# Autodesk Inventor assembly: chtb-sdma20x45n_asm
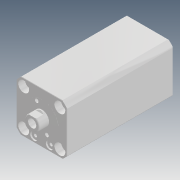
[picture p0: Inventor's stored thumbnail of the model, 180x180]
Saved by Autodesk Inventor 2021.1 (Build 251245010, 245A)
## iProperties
Created: 2018-05
Part Number: chtb-sdma20x45n_asm
Description: STEP AP214
Document SubType Name: Assembly
Designer: user
Title: chtb-sdma20x45n_asm.STEP
Revision Number: ÈÎºÎ
Sending System: SolidWorks 2016
Preprocessor: SwSTEP 2.0
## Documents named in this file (5)
- D:\Vault_2016\Projekty\Clamptek\Hydraulic\CHTB\CHTB-20\Inventor\CHTB-SDMA20x45N\chtb-sdma20x45n_asm.iam
- D:\Vault_2016\Projekty\Clamptek\Hydraulic\CHTB\CHTB-20\Inventor\CHTB-SDMA20x45N\CHTB-SDMA20X45NBT.ipt
- D:\Vault_2016\Projekty\Clamptek\Hydraulic\CHTB\CHTB-20\Inventor\CHTB-SDMA20x45N\CHTB-SDMA20X45NHSG.ipt
- D:\Vault_2016\Projekty\Clamptek\Hydraulic\CHTB\CHTB-20\Inventor\CHTB-SDMA20x45N\QG_3.ipt
- D:\Vault_2016\Projekty\Clamptek\Hydraulic\CHTB\CHTB-20\Inventor\CHTB-SDMA20x45N\socket set screw flat point_iso_ISO 4026 - M5 x 5-N.ipt
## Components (5 placed, 5 different names)
1. CHTB-SDMA20X45NBT_1
2. CHTB-SDMA20X45NHSG_2
3. QG_3_3
4. socket set screw flat point_iso_ISO 4026 - M5 x 5-N_4
5. socket set screw flat point_iso_ISO 4026 - M5 x 5-N_5
